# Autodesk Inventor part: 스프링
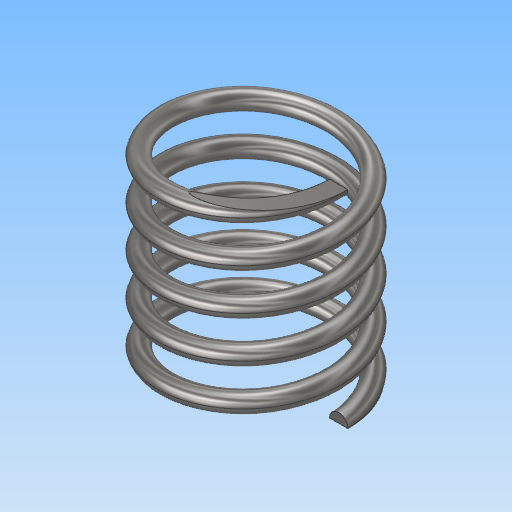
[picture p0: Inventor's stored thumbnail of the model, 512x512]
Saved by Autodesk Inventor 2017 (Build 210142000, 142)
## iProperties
Part Number: 스프링
Material: 스테인레스 스틸
Document SubType Name: Modeling
Designer: MRC
Density: 8 g/cm^3
Appearance: 반연마
Mass: 6.97199 g
Surface Area: 17.716 cm^2
Volume: 0.871499 cm^3
Author: MRC
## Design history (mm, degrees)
sketch "스케치1"
  geometry: L1 (0, 0)-(0, 22.5); L2 (0, 22.5)-(9, 22.5); L3 (0, 0)-(9, 0); C1 r 1 at (9, 0); 1 further point
  constraints: 6 end point, 2 coincident, 2 horizontal, 1 centre point, 1 vertical
  dimensions: "d0" = 22.5 distance of L1.start L1.end (derived); "d1" = 9 distance of L1.end L2.end; "d2" = 9 distance of L1.start L3.end; "d3" = 2 diameter of C1
feature "코일1" sketch "스케치1" pitch "d4" = 10; turns "d6" = 5; dims "d5" = 22.5 (= d0), "d7" = 0, angle "d8" = 90 deg, angle "d9" = 90 deg, "d10" = 0, "d11" = 0
sketch "스케치2"
  geometry: L1 (22.5, 15)-(0, 15); L2 (0, 15)-(0, -15); L3 (0, -15)-(22.5, -15); L4 (22.5, -15)-(22.5, 15); 2 further points
  constraints: 8 end point, 2 parallel, 1 coincident, 1 horizontal, 1 midpoint, 1 perpendicular
  dimensions: "d12" = 22.5 distance of L2.end L3.end (= d0); "d13" = 30 distance of L3.end L1.start
extrude "돌출1" sketch "스케치2" stored distance "d14" = 0; taper "d15" = 0 deg
node "솔리드1"
